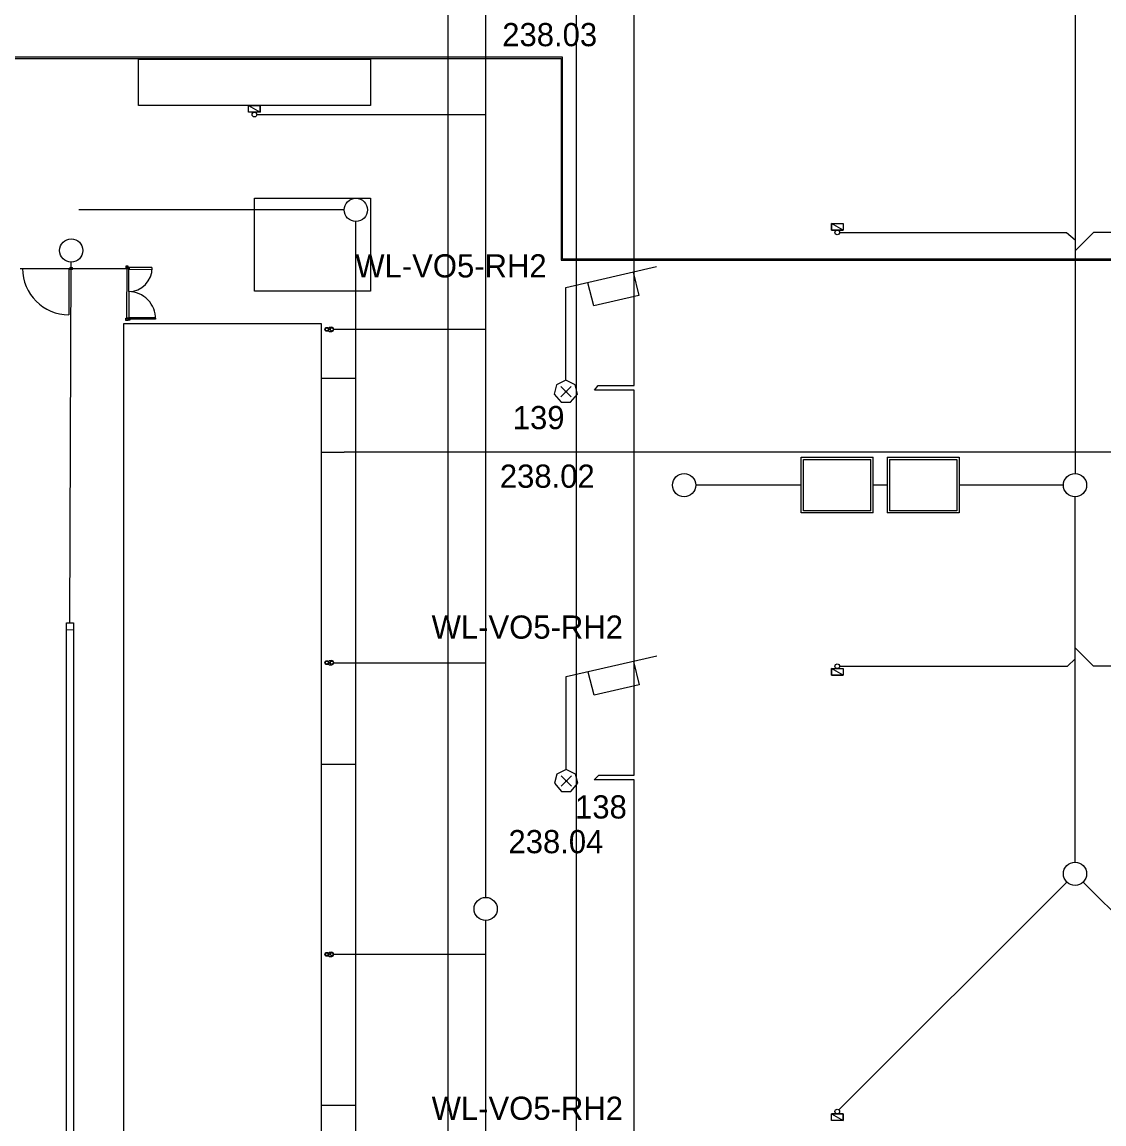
# Model space of a CAD drawing. Extents: x -264222 to -263592, y -1242345 to -1242048.
# Drawn here: x -263971.99 to -263925.35, y -1242232.3 to -1242184.78 of the extents above; entities that cross this region are included whole.
import ezdxf

# ---------------------------------------------------------------- set-up
doc = ezdxf.new("R2010")
doc.units = 0
for name, color, linetype in [('BOD_CISLO', 7, 'Continuous'), ('BOD_SYMBOL', 7, 'Continuous'), ('BOD_VYSKA', 7, 'Continuous'), ('KFA_2D_SITUACIA_DSP', 7, 'Continuous'), ('KFA_SO_62-1_VO_LAMPY_MERANE', 7, 'Continuous'), ('KFA_SO_62-1_VO_POPIS_LAMP_PROJEKT', 7, 'Continuous'), ('KFA_SO_62-1_VO_TRASA_KABLOV_PROJEKT', 7, 'Continuous')]:
    doc.layers.add(name, color=color, linetype=linetype)

msp = doc.modelspace()

# ---------------------------------------------------------------- linework, layer by layer
at = {"layer": 'BOD_SYMBOL'}
for p, q in [((-263948.763, -1242200.943), (-263948.321, -1242200.501)), ((-263948.321, -1242200.943), (-263948.763, -1242200.501)), ((-263948.749, -1242217.73), (-263948.307, -1242217.288)), ((-263948.307, -1242217.73), (-263948.749, -1242217.288))]:
    msp.add_line(p, q, dxfattribs=at)
at = {"layer": 'KFA_2D_SITUACIA_DSP'}
for p, q in [((-263948.093, -1242087.901), (-263948.093, -1242241.458)), ((-263953.617, -1242244.458), (-263953.617, -1242093.307)), ((-263926.593, -1242155.252), (-263926.593, -1242204.252)), ((-263952, -1242222.527), (-263952, -1242182)), ((-263962.218, -1242188.382), (-263961.718, -1242188.382)), ((-263962.218, -1242188.672), (-263962.218, -1242188.382)), ((-263962.218, -1242188.382), (-263961.718, -1242188.672)), ((-263962.218, -1242188.382), (-263961.718, -1242188.672)), ((-263961.718, -1242188.382), (-263962.218, -1242188.382)), ((-263961.718, -1242188.382), (-263961.718, -1242188.672)), ((-263961.718, -1242188.672), (-263961.718, -1242188.382)), ((-263961.718, -1242188.672), (-263962.218, -1242188.672)), ((-263961.868, -1242188.772), (-263952, -1242188.772)), ((-263958.097, -1242192.883), (-263969.542, -1242192.883)), ((-263957.597, -1242243.932), (-263957.597, -1242193.383)), ((-263937.093, -1242193.752), (-263937.093, -1242193.462)), ((-263937.093, -1242193.462), (-263936.593, -1242193.462)), ((-263936.593, -1242193.752), (-263937.093, -1242193.462)), ((-263936.593, -1242193.752), (-263937.093, -1242193.462)), ((-263937.093, -1242193.462), (-263937.093, -1242193.752)), ((-263936.593, -1242193.752), (-263937.093, -1242193.752)), ((-263937.093, -1242193.752), (-263936.593, -1242193.752)), ((-263936.593, -1242193.462), (-263936.593, -1242193.752)), ((-263936.743, -1242193.852), (-263926.953, -1242193.852)), ((-263926.953, -1242193.852), (-263926.593, -1242194.178)), ((-263925.798, -1242193.852), (-263926.593, -1242194.648)), ((-263920.944, -1242193.852), (-263925.798, -1242193.852)), ((-263969.921, -1242210.683), (-263969.869, -1242195.133)), ((-263972.068, -1242195.407), (-263967.418, -1242195.407)), ((-263969.968, -1242195.407), (-263969.968, -1242197.407)), ((-263967.413, -1242195.307), (-263967.513, -1242195.307)), ((-263967.513, -1242195.307), (-263967.513, -1242195.407)), ((-263967.513, -1242195.407), (-263967.413, -1242195.407)), ((-263967.425, -1242195.32), (-263967.5, -1242195.32)), ((-263967.5, -1242195.32), (-263967.5, -1242195.395)), ((-263967.5, -1242195.395), (-263967.425, -1242195.395)), ((-263967.463, -1242195.407), (-263967.463, -1242196.395)), ((-263967.388, -1242195.407), (-263967.463, -1242195.407)), ((-263967.425, -1242195.395), (-263967.425, -1242195.32)), ((-263967.425, -1242195.395), (-263967.425, -1242195.345)), ((-263967.425, -1242195.345), (-263967.325, -1242195.345)), ((-263967.413, -1242195.407), (-263967.413, -1242195.307)), ((-263967.413, -1242195.357), (-263967.363, -1242195.357)), ((-263967.388, -1242196.395), (-263967.388, -1242195.407)), ((-263967.363, -1242195.457), (-263967.388, -1242195.457)), ((-263966.388, -1242195.371), (-263967.375, -1242195.37)), ((-263967.375, -1242195.37), (-263967.375, -1242195.445)), ((-263967.375, -1242195.445), (-263966.388, -1242195.446)), ((-263967.363, -1242195.357), (-263967.363, -1242195.457)), ((-263967.325, -1242195.345), (-263967.325, -1242195.37)), ((-263967.463, -1242197.557), (-263967.463, -1242196.42)), ((-263967.388, -1242196.42), (-263967.388, -1242197.557)), ((-263967.513, -1242197.557), (-263967.413, -1242197.557)), ((-263967.513, -1242197.657), (-263967.513, -1242197.557)), ((-263967.5, -1242197.57), (-263967.425, -1242197.57)), ((-263967.5, -1242197.645), (-263967.5, -1242197.57)), ((-263967.388, -1242197.557), (-263967.463, -1242197.557)), ((-263967.425, -1242197.57), (-263967.425, -1242197.62)), ((-263967.425, -1242197.57), (-263967.425, -1242197.645)), ((-263967.425, -1242197.62), (-263967.325, -1242197.62)), ((-263967.413, -1242197.557), (-263967.413, -1242197.657)), ((-263967.413, -1242197.607), (-263967.363, -1242197.607)), ((-263967.363, -1242197.507), (-263967.388, -1242197.507)), ((-263967.375, -1242197.52), (-263966.238, -1242197.52)), ((-263967.375, -1242197.595), (-263967.375, -1242197.52)), ((-263966.238, -1242197.595), (-263967.375, -1242197.595)), ((-263967.363, -1242197.607), (-263967.363, -1242197.507)), ((-263967.325, -1242197.62), (-263967.325, -1242197.595)), ((-263967.593, -1242252.182), (-263967.593, -1242197.782)), ((-263967.593, -1242197.782), (-263959.093, -1242197.782)), ((-263967.593, -1242197.782), (-263959.097, -1242197.782)), ((-263967.593, -1242252.182), (-263967.593, -1242197.782)), ((-263967.413, -1242197.657), (-263967.513, -1242197.657)), ((-263967.425, -1242197.645), (-263967.5, -1242197.645)), ((-263967.478, -1242197.782), (-263967.358, -1242197.782)), ((-263959.097, -1242197.782), (-263959.093, -1242252.182)), ((-263959.093, -1242197.782), (-263959.093, -1242252.182)), ((-263958.799, -1242197.962), (-263958.762, -1242197.962)), ((-263958.762, -1242197.962), (-263958.742, -1242197.942)), ((-263958.742, -1242197.942), (-263958.637, -1242197.942)), ((-263958.575, -1242198.032), (-263952, -1242198.032)), ((-263958.799, -1242198.102), (-263958.762, -1242198.102)), ((-263958.762, -1242198.102), (-263958.742, -1242198.122)), ((-263958.742, -1242198.122), (-263958.637, -1242198.122)), ((-263959.097, -1242200.132), (-263957.597, -1242200.132)), ((-263959.097, -1242203.332), (-263958.097, -1242203.332)), ((-263924.893, -1242203.332), (-263958.097, -1242203.332)), ((-263938.393, -1242203.552), (-263935.293, -1242203.552)), ((-263938.393, -1242205.952), (-263938.393, -1242203.552)), ((-263938.293, -1242205.852), (-263938.293, -1242203.652)), ((-263938.293, -1242203.652), (-263935.393, -1242203.652)), ((-263935.393, -1242205.852), (-263935.393, -1242203.652)), ((-263935.293, -1242205.952), (-263935.293, -1242203.552)), ((-263934.693, -1242203.552), (-263931.593, -1242203.552)), ((-263934.693, -1242203.552), (-263934.693, -1242205.952)), ((-263934.593, -1242203.652), (-263934.593, -1242205.852)), ((-263934.593, -1242203.652), (-263931.693, -1242203.652)), ((-263931.693, -1242203.652), (-263931.693, -1242205.852)), ((-263931.593, -1242203.552), (-263931.593, -1242205.952)), ((-263938.393, -1242204.752), (-263942.945, -1242204.752)), ((-263934.693, -1242204.752), (-263935.293, -1242204.752)), ((-263927.093, -1242204.752), (-263931.593, -1242204.752)), ((-263926.593, -1242221.011), (-263926.593, -1242205.252)), ((-263935.293, -1242205.952), (-263938.393, -1242205.952)), ((-263935.393, -1242205.852), (-263938.293, -1242205.852)), ((-263931.593, -1242205.952), (-263934.693, -1242205.952)), ((-263931.693, -1242205.852), (-263934.593, -1242205.852)), ((-263970.071, -1242210.684), (-263969.77, -1242210.682)), ((-263970.07, -1242239.282), (-263970.071, -1242210.684)), ((-263969.77, -1242210.682), (-263969.77, -1242239.282)), ((-263970.071, -1242210.983), (-263969.771, -1242210.985)), ((-263925.798, -1242212.562), (-263926.593, -1242211.767)), ((-263958.799, -1242212.337), (-263958.762, -1242212.337)), ((-263958.762, -1242212.337), (-263958.742, -1242212.317)), ((-263958.742, -1242212.317), (-263958.637, -1242212.317)), ((-263926.919, -1242212.562), (-263926.593, -1242212.237)), ((-263958.799, -1242212.477), (-263958.762, -1242212.477)), ((-263958.762, -1242212.477), (-263958.742, -1242212.497)), ((-263958.742, -1242212.497), (-263958.637, -1242212.497)), ((-263958.575, -1242212.407), (-263952, -1242212.407)), ((-263937.093, -1242212.952), (-263937.093, -1242212.662)), ((-263937.093, -1242212.662), (-263936.593, -1242212.662)), ((-263936.593, -1242212.952), (-263937.093, -1242212.662)), ((-263936.593, -1242212.952), (-263937.093, -1242212.662)), ((-263937.093, -1242212.662), (-263937.093, -1242212.952)), ((-263936.743, -1242212.562), (-263926.919, -1242212.562)), ((-263936.593, -1242212.662), (-263936.593, -1242212.952)), ((-263916.443, -1242212.562), (-263925.798, -1242212.562)), ((-263936.593, -1242212.952), (-263937.093, -1242212.952)), ((-263937.093, -1242212.952), (-263936.593, -1242212.952)), ((-263959.097, -1242216.782), (-263957.597, -1242216.782)), ((-263936.772, -1242231.691), (-263926.947, -1242221.865)), ((-263916.414, -1242231.691), (-263926.24, -1242221.865)), ((-263952, -1242251.432), (-263952, -1242223.527)), ((-263958.799, -1242224.912), (-263958.762, -1242224.912)), ((-263958.799, -1242225.052), (-263958.762, -1242225.052)), ((-263958.762, -1242224.912), (-263958.742, -1242224.892)), ((-263958.762, -1242225.052), (-263958.742, -1242225.072)), ((-263958.742, -1242224.892), (-263958.637, -1242224.892)), ((-263958.742, -1242225.072), (-263958.637, -1242225.072)), ((-263958.575, -1242224.982), (-263952, -1242224.982)), ((-263959.097, -1242231.482), (-263957.597, -1242231.482)), ((-263937.093, -1242231.862), (-263936.593, -1242231.862)), ((-263937.093, -1242232.152), (-263937.093, -1242231.862)), ((-263937.093, -1242231.862), (-263936.593, -1242232.152)), ((-263937.093, -1242231.862), (-263936.593, -1242232.152)), ((-263936.593, -1242231.862), (-263937.093, -1242231.862)), ((-263936.593, -1242232.152), (-263937.093, -1242232.152)), ((-263936.593, -1242231.862), (-263936.593, -1242232.152)), ((-263936.593, -1242232.152), (-263936.593, -1242231.862))]:
    msp.add_line(p, q, dxfattribs=at)
for points in [[(-263966.968, -1242186.382), (-263956.968, -1242186.382), (-263956.968, -1242188.382), (-263966.968, -1242188.382)], [(-263961.968, -1242192.382), (-263956.968, -1242192.382), (-263956.968, -1242196.382), (-263961.968, -1242196.382)], [(-263967.597, -1242197.782), (-263959.097, -1242197.782), (-263959.097, -1242252.182), (-263967.597, -1242252.182)]]:
    msp.add_lwpolyline(points, close=True, dxfattribs=at)
for centre, radius in [((-263961.968, -1242188.772), 0.1), ((-263957.597, -1242192.883), 0.5), ((-263936.843, -1242193.852), 0.1), ((-263969.868, -1242194.633), 0.5), ((-263969.868, -1242195.407), 0.06), ((-263958.847, -1242198.032), 0.085), ((-263958.847, -1242198.032), 0.0625), ((-263958.637, -1242198.032), 0.0625), ((-263943.445, -1242204.752), 0.5), ((-263926.593, -1242204.752), 0.5), ((-263958.847, -1242212.407), 0.085), ((-263958.847, -1242212.407), 0.0625), ((-263958.637, -1242212.407), 0.0625), ((-263936.843, -1242212.562), 0.1), ((-263926.593, -1242221.511), 0.5), ((-263952, -1242223.027), 0.5), ((-263958.847, -1242224.982), 0.085), ((-263958.847, -1242224.982), 0.0625), ((-263958.637, -1242224.982), 0.0625), ((-263936.843, -1242231.762), 0.1)]:
    msp.add_circle(centre, radius, dxfattribs=at)
for centre, radius, start, end in [((-263969.968, -1242195.407), 2, 180, 270), ((-263967.4, -1242195.382), 1.025, 270.6095, 0.6095), ((-263967.4, -1242197.582), 1.175, 359.3905, 89.3905), ((-263958.637, -1242198.032), 0.09, 270, 90), ((-263958.637, -1242212.407), 0.09, 270, 90), ((-263958.637, -1242224.982), 0.09, 270, 90)]:
    msp.add_arc(centre, radius, start, end, dxfattribs=at)
for centre in [(-263967.4, -1242195.382), (-263967.4, -1242195.382), (-263967.4, -1242197.582)]:
    msp.add_ellipse(centre, major_axis=(0, 0.0125), ratio=0.999995, dxfattribs=at)
at = {"layer": 'KFA_SO_62-1_VO_LAMPY_MERANE'}
for p, q in [((-263948.592, -1242200.722), (-263948.492, -1242200.722)), ((-263948.542, -1242200.722), (-263948.542, -1242200.722)), ((-263948.578, -1242217.509), (-263948.478, -1242217.509)), ((-263948.528, -1242217.509), (-263948.528, -1242217.509))]:
    msp.add_line(p, q, dxfattribs=at)
for points in [[(-263948.542, -1242200.222), (-263948.942, -1242200.422), (-263949.042, -1242200.822), (-263948.742, -1242201.172), (-263948.342, -1242201.172), (-263948.042, -1242200.822), (-263948.142, -1242200.422), (-263948.542, -1242200.222), (-263948.542, -1242196.222), (-263944.642, -1242195.322)], [(-263945.642, -1242195.572), (-263945.392, -1242196.572), (-263947.342, -1242197.022), (-263947.592, -1242196.022)], [(-263948.528, -1242217.009), (-263948.928, -1242217.209), (-263949.028, -1242217.609), (-263948.728, -1242217.959), (-263948.328, -1242217.959), (-263948.028, -1242217.609), (-263948.128, -1242217.209), (-263948.528, -1242217.009), (-263948.528, -1242213.009), (-263944.628, -1242212.109)], [(-263945.628, -1242212.359), (-263945.378, -1242213.359), (-263947.328, -1242213.809), (-263947.578, -1242212.809)]]:
    msp.add_lwpolyline(points, dxfattribs=at)
at = {"layer": 'KFA_SO_62-1_VO_TRASA_KABLOV_PROJEKT'}
for p, q in [((-263945.593, -1242200.459), (-263945.593, -1242183.86)), ((-263948.695, -1242186.3), (-264119.795, -1242186.3)), ((-263979.095, -1242186.35), (-263948.745, -1242186.35)), ((-263948.745, -1242186.35), (-263948.745, -1242195.05)), ((-263948.695, -1242195), (-263948.695, -1242186.3)), ((-263948.745, -1242195.05), (-263913.645, -1242195.05)), ((-263913.695, -1242195), (-263948.695, -1242195)), ((-263947.31, -1242200.657), (-263947.15, -1242200.459)), ((-263947.15, -1242200.459), (-263945.593, -1242200.459)), ((-263945.592, -1242200.657), (-263947.31, -1242200.657)), ((-263945.592, -1242217.257), (-263945.592, -1242200.657)), ((-263947.317, -1242217.457), (-263947.117, -1242217.257)), ((-263945.593, -1242217.457), (-263947.317, -1242217.457)), ((-263947.117, -1242217.257), (-263945.592, -1242217.257)), ((-263945.593, -1242237.814), (-263945.593, -1242217.457))]:
    msp.add_line(p, q, dxfattribs=at)

# ---------------------------------------------------------------- texts
at = {"layer": 'BOD_CISLO'}
for s, p in [('139', (-263950.831, -1242202.338)), ('138', (-263948.146, -1242219.127))]:
    msp.add_text(s, height=1, dxfattribs=at).set_placement(p)
at = {"layer": 'BOD_VYSKA'}
for s, p in [('238.03', (-263951.285, -1242185.824)), ('238.02', (-263951.389, -1242204.864)), ('238.04', (-263951.017, -1242220.623))]:
    msp.add_text(s, height=1, dxfattribs=at).set_placement(p)
at = {"layer": 'KFA_SO_62-1_VO_POPIS_LAMP_PROJEKT'}
for p in [(-263957.62, -1242195.796), (-263954.329, -1242211.372), (-263954.329, -1242232.12)]:
    msp.add_text('WL-VO5-RH2', height=1, dxfattribs=at).set_placement(p)

doc.saveas('drawing.dxf')
